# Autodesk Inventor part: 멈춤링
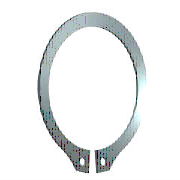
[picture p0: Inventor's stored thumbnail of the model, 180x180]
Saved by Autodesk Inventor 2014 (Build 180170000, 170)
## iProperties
IsCustomPart: 1
Created: 2012-02
Part Number: 멈춤링
Material: 강철, 연강
Description: 리테이닝 링(C형)
Document SubType Name: Modeling
Standard: KS B 1336
Designer: mduedu
Standards Organization: KS
Language: ko-KR
Size Designation: 20 x 1.2
Categories: <MemberInstance><Categories><Category DisplayName="샤프트 부품" InternalName="7f7aeb1f-a693-4053-b835-cee3144e0d98" Mnemonic="SHFT"><Category DisplayName="써클립" Inter
Density: 7.86 g/cm^3
Appearance: 노란색
Mass: 1.66547 g
Surface Area: 5.4075 cm^2
Volume: 0.211892 cm^3
Author: mduedu
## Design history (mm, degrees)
sketch "스케치1"
  geometry: L1 (-6, 0)-(6, 0) reference; L2 (0, 20.189)-(0, -80.536) reference; L3 (-48.09, 0)-(48.09, 0) reference; L4 (-0.5, -19.487)-(-0.5, -23.387); L5 (-0.5, -6.54)-(-0.5, -13.29); L6 (-2.795, 2.7)-(3.672, 2.7); L7 (0.5, -6.54)-(0.5, -13.29); L8 (0.5, -19.487)-(0.5, -23.387); C1 r 1 at (-2, -21.219); C2 r 1 at (2, -21.219); A1 r 9.5 centre (0, -10) between (0.5, -19.487) and (-0.5, -19.487); A2 r 12.025 centre (0, -9.325) between (5.071, -20.228) and (-5.071, -20.228); A3 r 13.396 centre (0, -10) between (-2.351, -23.188) and (-0.5, -23.387); A4 r 2 centre (-2, -21.219) between (-3.957, -21.631) and (-2.351, -23.188); A5 r 2 centre (-5.915, -22.042) between (-3.957, -21.631) and (-5.071, -20.228); A6 r 2 centre (5.915, -22.042) between (5.071, -20.228) and (3.957, -21.631); A7 r 2 centre (2, -21.219) between (2.351, -23.188) and (3.957, -21.631); A8 r 13.396 centre (0, -10) between (0.5, -23.387) and (2.351, -23.188)
  constraints: 16 point on circle, 12 end point, 10 centre point, 9 symmetric about line, 5 point on line, 4 tangent, 3 coincident, 2 horizontal, 1 perpendicular, 1 vertical, 5 other
  dimensions: "d0" = 19 diameter of A1 (= ND); "d1" = 3.9 distance of L4.end L4.start (= SRB2); "d6" = 0.5 distance between parallel lines of L2 L5 (= 0.25 x SD5); "d7" = 2.7 distance between parallel lines of L6 L3 (= SRB1); "d8" = 0.675 distance of A1.centre A2.centre (= 0.25 x SRB1); "d9" = 2 radius of A4 (= SD5); "d10" = 2 radius of A5 (= SD5); "d11" = 1.5 distance from line of L4 A4.centre (= 0.75 x SD5); "d12" = 2 diameter of C1 (= SD5); "d13" = 2 diameter of C2 (= SD5); "d14" = 10 distance from line of A1.centre L1 (= 0.5 x WD)
extrude "본체" new body sketch "스케치1" distance "d2" = 1.2 (= SD); taper "d3" = 0 deg
workaxis "Work Axis1"
workplane "Work Plane1"
body "Solid1"
other parameters: "SD" = 1.2 [user parameter; used in 1 equation term], "SRB1" = 2.7 [user parameter; used in 2 equation terms], "ND" = 19 [user parameter; used in 1 equation term], "SRB2" = 3.9 [user parameter; used in 1 equation term], "SD5" = 2 [user parameter; used in 6 equation terms], "d15" = 0, "d16" = 0, "d17" = 0, "d41" = 0, "d42" = 0, "SD3" = 18.5 [user parameter], "WDMAX" = 21 [user parameter]
